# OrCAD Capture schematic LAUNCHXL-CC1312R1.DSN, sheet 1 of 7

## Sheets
1 6_EnergyTrace Power: size A3; title: LAUNCHXL-CC1312R1; rev: B; company: Texas Instruments
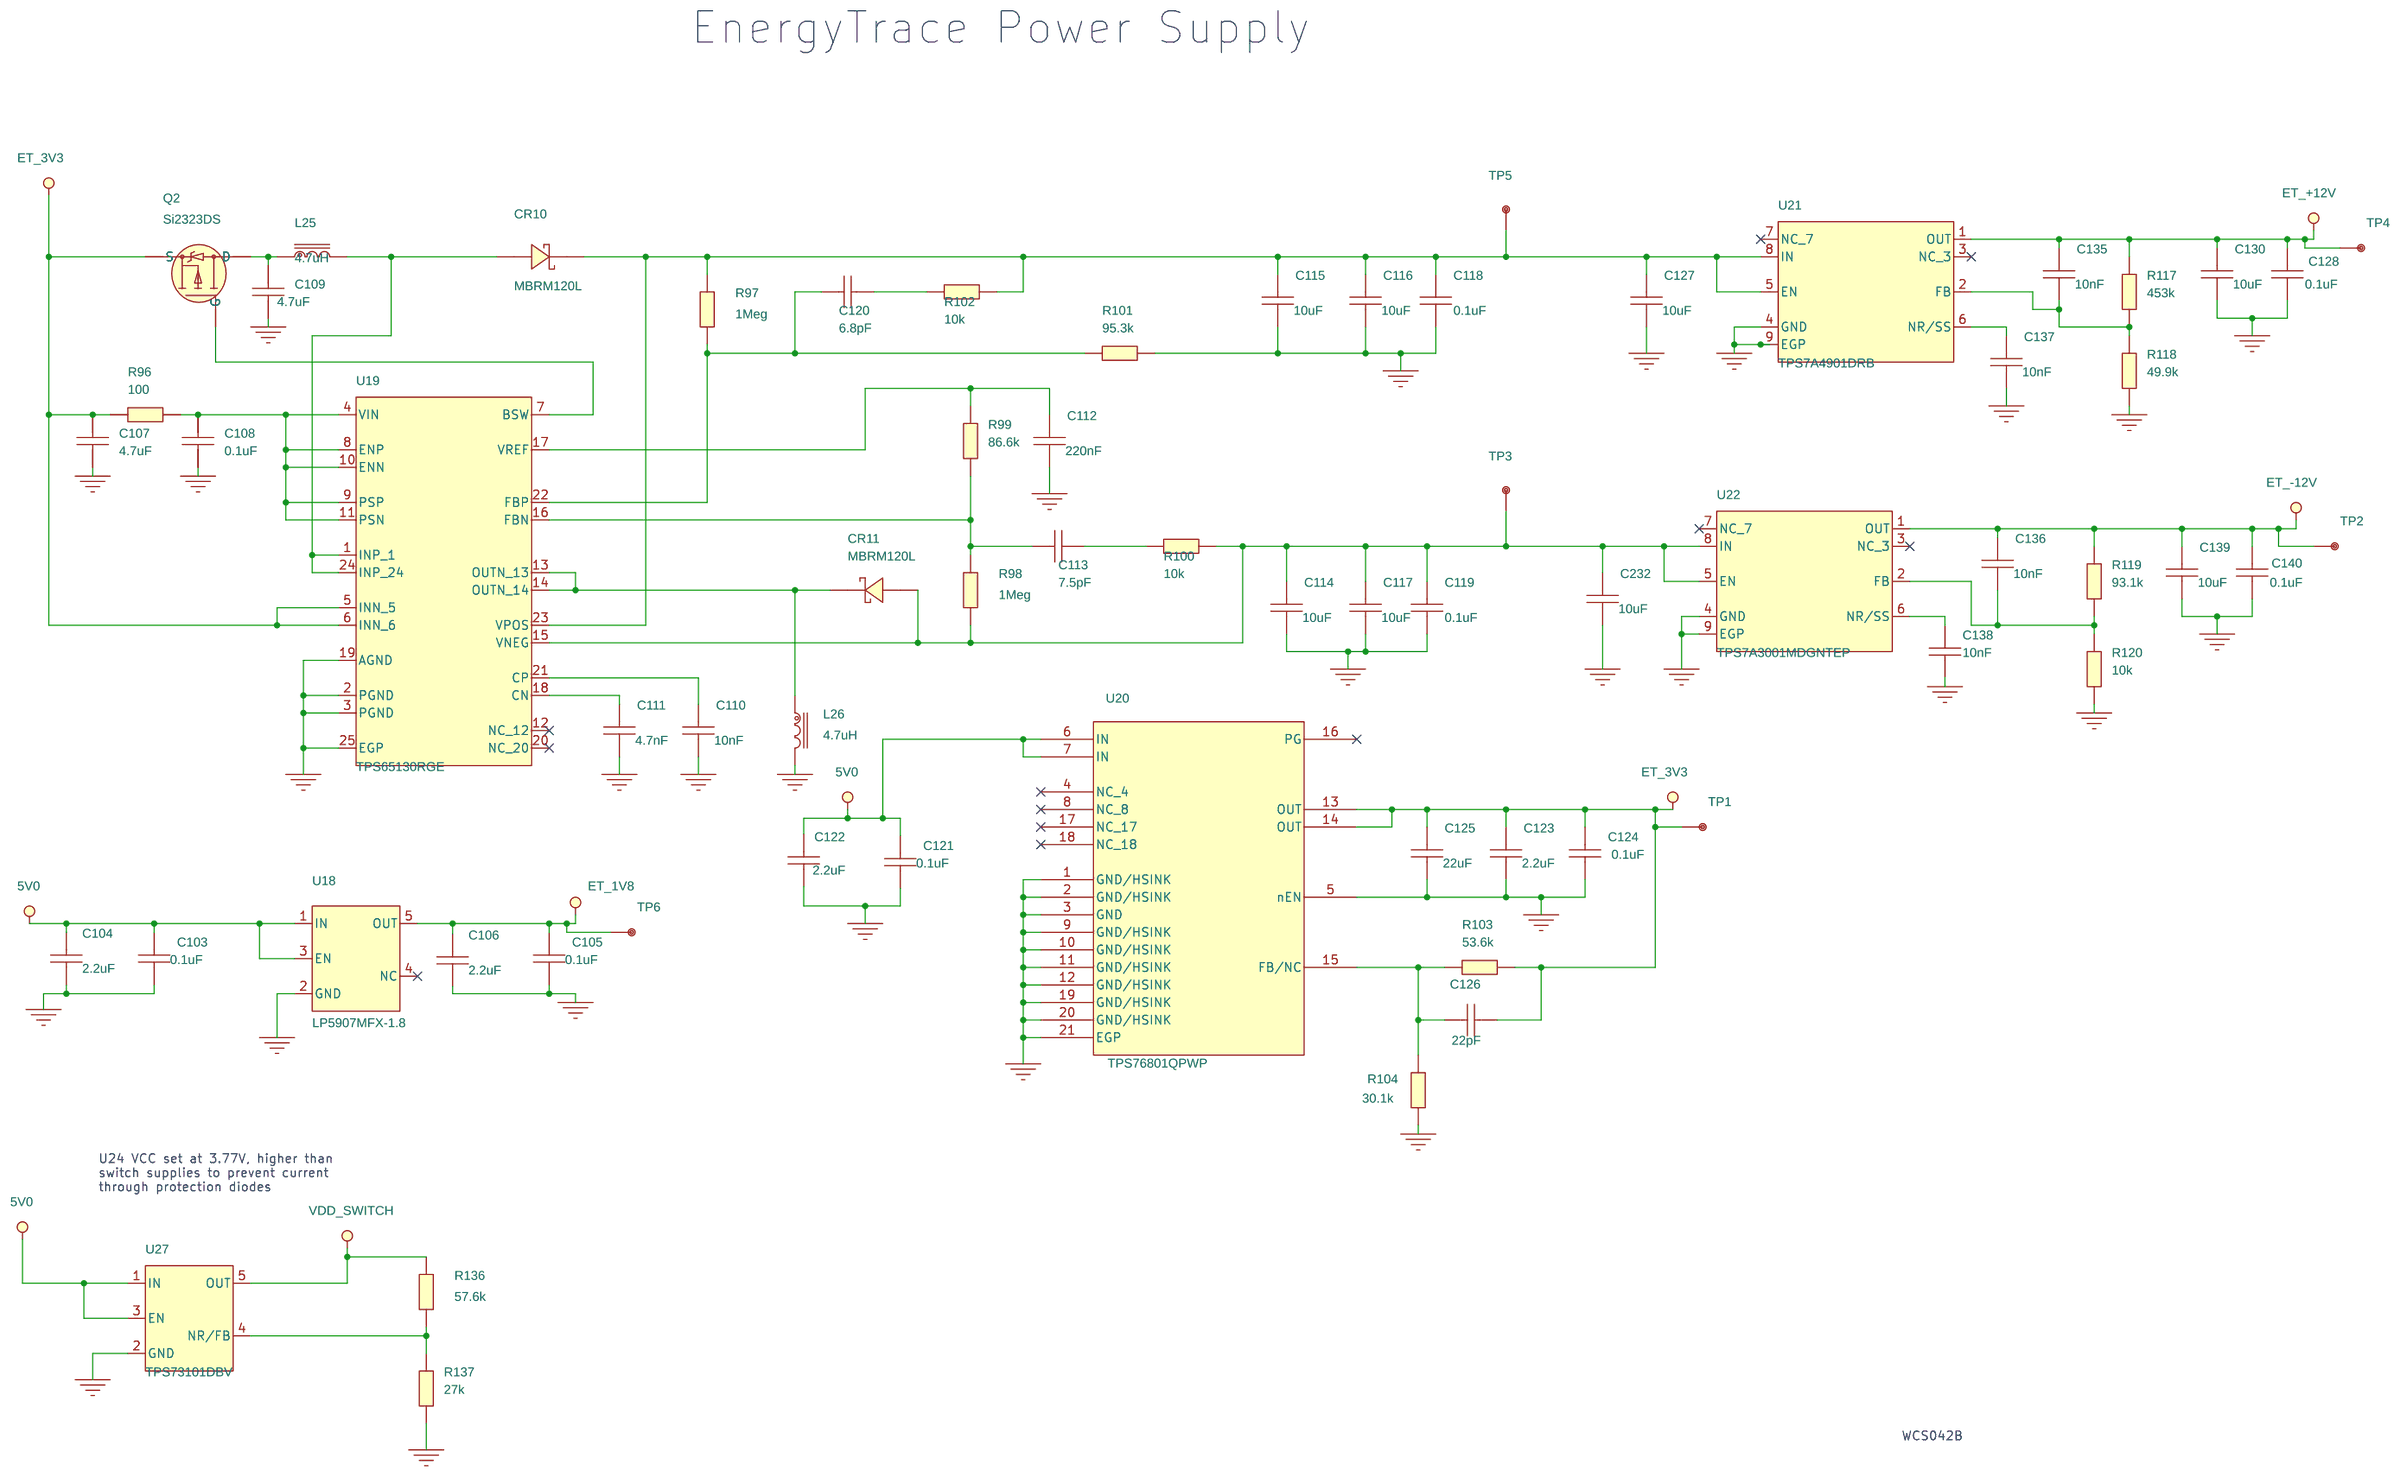
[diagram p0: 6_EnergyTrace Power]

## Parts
C103  0.1uF  [CAPC1005X60B2N]
C104  2.2uF  [CAPC1005X60B2N]
C105  0.1uF  [CAPC1005X60B2N]
C106  2.2uF  [CAPC1005X60B2N]
C107  4.7uF  [CAPC1005X60B2N]
C108  0.1uF  [CAPC1005X60B2N]
C109  4.7uF  [CAPC2012X150A2N]
C110  10nF  [CAPC1005X60B2N]
C111  4.7nF  [CAPC1005X60N]
C112  220nF  [CAPC1005X60A2N]
C113  7.5pF  [CAPC1005X60B2N]
C114  10uF  [CAPC2012X150A2N]
C115  10uF  [CAPC2012X150A2N]
C116  10uF  [CAPC2012X150A2N]
C117  10uF  [CAPC2012X150A2N]
C118  0.1uF  [CAPC1005X60B2N]
C119  0.1uF  [CAPC1005X60B2N]
C120  6.8pF  [CAPC1005X60B2N]
C121  0.1uF  [CAPC1005X60B2N]
C122  2.2uF  [CAPC1005X60B2N]
C123  2.2uF  [CAPC1005X60B2N]
C124  0.1uF  [CAPC1005X60B2N]
C125  22uF  [CAPC1608X100A2N]
C126  22pF  [CAPC1005X60B2N]
C127  10uF  [CAPC2012X150A2N]
C128  0.1uF  [CAPC1005X60B2N]
C130  10uF  [CAPC2012X150A2N]
C135  10nF  [CAPC1005X60B2N]
C136  10nF  [CAPC1005X60B2N]
C137  10nF  [CAPC1005X60B2N]
C138  10nF  [CAPC1005X60B2N]
C139  10uF  [CAPC2012X150A2N]
C140  0.1uF  [CAPC1005X60B2N]
C232  10uF  [CAPC2012X150A2N]
CR10  MBRM120L  [DIO_MBRM120_A2N]
CR11  MBRM120L  [DIO_MBRM120_A2N]
L25  4.7uH  [IND_7447789004N]
L26  4.7uH  [IND_7447789004N]
Q2  Si2323DS  [SOT95P237X130-3N]
R96  100  [RESC1005X40B2N]
R97  1Meg  [RESC1005X40B2N]
R98  1Meg  [RESC1005X40B2N]
R99  86.6k  [RESC1005X40N]
R100  10k  [RESC1005X40B2N]
R101  95.3k  [RESC1005X40N]
R102  10k  [RESC1005X40B2N]
R103  53.6k  [RESC1005X40N]
R104  30.1k  [RESC1005X40N]
R117  453k  [RESC1005X40N]
R118  49.9k  [RESC1005X40N]
R119  93.1k  [RESC1005X40N]
R120  10k  [RESC1005X40A2N]
R136  57.6k  [RESC1005X40A2N]
R137  27k  [RESC1005X40A2N]
TP1  HOLE_0.6mm_PTH  [MTG60_120]
TP2  HOLE_0.6mm_PTH  [MTG60_120]
TP3  HOLE_0.6mm_PTH  [MTG60_120]
TP4  HOLE_0.6mm_PTH  [MTG60_120]
TP5  HOLE_0.6mm_PTH  [MTG60_120]
TP6  HOLE_0.6mm_PTH  [MTG60_120]
U18  LP5907MFX-1.8  [SOT95P280X145-5A2N]
U19  TPS65130RGE  [QFNFC50P400X400X100-25D2N]
U20  TPS76801QPWP  [TSSOP65P640X120-21N]
U21  TPS7A4901DRB  [SON65P300X300X100-9A2N]
U22  TPS7A3001MDGNTEP  [SOP65P490X110-9B2N]
U27  TPS73101DBV  [SOT95P280X145-5A2N]

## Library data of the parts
C103 C105 C108 C118 C119 C121 C124 C128 C140 = CAPACITOR: CAPACITOR, CERAMIC X7R, 0.1uF, 25V, -10%/+10%, -55DEGC/+125DEGC, 0402, SMD; AutoDoc File: https://notefied-dynamic-precision.com/DB/Apps/Desktop/Item/Object.aspx?id=115293; BU Name: TEXAS INSTRUMENTS NORWAY; Client Status: UNDER_REVIEW; Datasheet URL 1: http://psearch.en.murata.com/capacitor/product/GRM155R71E104KE14%23.pdf; Datasheet URL 2: http://search.murata.co.jp/Ceramy/image/img/w_hinm/L0005E.pdf; Dielectric Type: X7R; Last Time Buy: N/A; LifeCycle Status: ACTIVE; MPN: GRM155R70J104KA01D; MPN Status: ACTIVE; Manufacturer: MURATA; Max Oper Temp: +125DEGC; Max Tol: +10%; Min Oper Temp: -55DEGC; Min Tol: -10%; Mounting Type: SMD; NOTE Status: PREFERRED; Old Footprint: CAPC1005X60N,0402; PCB Package: 0402; Packing Size: 10000; Packing Type: TAPE_&_REEL; Part Number: 02-07861; Part Type: CAPACITOR\CERAMIC\0402\STANDARD; REACH/SVHC_COMPLIANCE: COMPLIANT; REACH/SVHC_DETAILS: SVHC LIST VERSION Jun 20, 2016; REACH/SVHC_SOURCE: REACH DECLARATION; REACH/SVHC_STATUS: UNAFFECTED; Revision: R002; RoHS Status: ROHS_COMPLIANT; Rtd Voltage: 25V; Vendor: MURATA; Vendor Part Number: GRM155R71E104KE14D; Vendor Part Status: ACTIVE; WEIGHT: 0.0016g
C104 C106 C122 C123 = CAPACITOR: CAPACITOR, CERAMIC X5R, 2.2uF, 6.3V, -10%/+10%, -55DEGC/+85DEGC, 0402, SMD; AutoDoc File: https://notefied-dynamic-precision.com/DB/Apps/Desktop/Item/Object.aspx?id=113352; BU Name: TEXAS INSTRUMENTS NORWAY; Budget Currency: USD; Budget Price: 0.0126; Country of Origin: PHILIPPINES; Datasheet URL 1: http://psearch.murata.com/capacitor/product/GRM155R60J225KE95%23.pdf; Datasheet URL 2: http://psearch.en.murata.com/capacitor/product/GRM155R60J225KE95%23.html; Dielectric Type: X5R; Last Time Buy: N/A; Lead Time: N/A; Max Oper Temp: +85DEGC; Max Tol: +10%; Min Oper Temp: -55DEGC; Min Tol: -10%; Mounting Type: SMD; PCB Package: 0402; Packing Size: 10000; Packing Type: TAPE_&_REEL; Part Number: 02-07624; Part Type: CAPACITOR\CERAMIC\0402\STANDARD; Revision: R000; RoHS Status: ROHS_COMPLIANT; Rtd Voltage: 6.3V; Vendor: MURATA; Vendor Part Number: GRM155R60J225KE95D; Vendor Part Status: NRND; Weight: 0.0016g
C107 = CAPACITOR: CAPACITOR, CERAMIC X5R, 4.7uF, 6.3V, -20%/+20%, -55DEGC/+85DEGC, 0402, SMD; AutoDoc File: https://notefied-dynamic-precision.com/DB/Apps/Desktop/Item/Object.aspx?id=113357; BU Name: TEXAS INSTRUMENTS NORWAY; Budget Currency: USD; Budget Price: 0.03; Country of Origin: PHILIPPINES; Datasheet URL 1: http://psearch.murata.com/capacitor/product/GRM155R60J475ME87%23.pdf; Datasheet URL 2: http://search.murata.co.jp/Ceramy/image/img/w_hinm/L0005E.pdf; Dielectric Type: X5R; Last Time Buy: N/A; Lead Time: 14; Max Oper Temp: +85DEGC; Max Tol: +20%; Min Oper Temp: -55DEGC; Min Tol: -20%; Mounting Type: SMD; PCB Package: 0402; Packing Size: 10000; Packing Type: TAPE_&_REEL; Part Number: 02-07629; Part Type: CAPACITOR\CERAMIC\0402\STANDARD; REACH/SVHC_COMPLIANCE: COMPLIANT; REACH/SVHC_DETAILS: SVHC LIST VERSION Dec 17, 2015; REACH/SVHC_SOURCE: REACH DECLARATION; REACH/SVHC_STATUS: UNAFFECTED; Revision: R000; RoHS Status: ROHS_COMPLIANT; Rtd Voltage: 6.3V; Vendor: MURATA; Vendor Part Number: GRM155R60J475ME87D; Vendor Part Status: NRND; Weight: 0.0025g
C109 = CAPACITOR: CAPACITOR, CERAMIC X7R, 4.7uF, 25V, -10%/+10%, -55DEGC/+125DEGC, 0805, SMD; ALT_SYMBOLS: CAPC2012X150A2L,CAPC2012X150A2M; AutoDoc File: https://notefied-dynamic-precision.com/DB/Apps/Desktop/Item/Object.aspx?id=100426; BU Name: DYNAMIC PRECISION GDANSK; Budget Currency: EUR; Budget Price: 0.165; Client Status: UNDER_REVIEW; Country of Origin: JAPAN,CHINA; Datasheet URL 1: http://product.tdk.com/info/en/documents/chara_sheet/C2012X7R1E475K125AB.pdf; Datasheet URL 2: http://product.tdk.com/info/en/catalog/datasheets/mlcc_commercial_general_en.pdf; Dielectric Type: X7R; Last Time Buy: N/A; Lead Time: 14; Max Oper Temp: +125DEGC; Max Tol: +10%; Min Oper Temp: -55DEGC; Min Tol: -10%; Mounting Type: SMD; PCB Package: 0805; Packing Size: 2000; Packing Type: TAPE_&_REEL; Part Number: 02-06852; Part Type: CAPACITOR\CERAMIC\0805\STANDARD; Revision: R001; RoHS Status: ROHS_COMPLIANT; Rtd Voltage: 25V; Vendor: TDK; Vendor Part Number: C2012X7R1E475K125AB; Vendor Part Status: ACTIVE; Weight: 0.01563g
C110 C135-C138 = CAPACITOR: CAPACITOR, CERAMIC X7R, 10nF, 25V, -10%/+10%, -55DEGC/+125DEGC, 0402, SMD; AutoDoc File: https://notefied-dynamic-precision.com/DB/Apps/Desktop/Item/Object.aspx?id=114570; BU Name: TEXAS INSTRUMENTS NORWAY; Budget Currency: EUR; Budget Price: 0.003; Client Status: UNDER_REVIEW; Country of Origin: JAPAN,CHINA; Datasheet URL 1: http://psearch.murata.com/capacitor/product/GRM155R71E103KA01%23.pdf; Datasheet URL 2: http://search.murata.co.jp/Ceramy/image/img/w_hinm/L0005E.pdf; Definied Quality: INDUSTRIAL; Dielectric Type: X7R; Esd Level: N/A; Last Time Buy: N/A; Lead Time: 18; LifeCycle Status: ACTIVE; MPN: CAPACITOR_0402_10nF_X7R_M_+/-10%_25V; MPN Status: ACTIVE; MSL: N/A; MTBF: N/A; MTBF Standard: N/A; Manufacturer: MANUFACTURER SELECTION; Max Oper Temp: +125DEGC; Max Tol: +10%; Min Oper Temp: -55DEGC; Min Tol: -10%; Mounting Type: SMD; NOTE Status: PREFERRED; Old Footprint: CAPC1005X60N; PCB Package: 0402; Packing Size: 10000; Packing Type: TAPE_&_REEL; Part Number: 02-07775; Part Type: CAPACITOR\CERAMIC\0402\STANDARD; REACH/SVHC_COMPLIANCE: COMPLIANT; REACH/SVHC_DETAILS: SVHC LIST VERSION Dec 17, 2015; REACH/SVHC_SOURCE: MATERIAL DECLARATION; REACH/SVHC_STATUS: UNAFFECTED; Revision: R000; RoHS Status: ROHS_COMPLIANT; Rtd Voltage: 25V; Vendor: MURATA; Vendor Part Number: GRM155R71E103KA01D; Vendor Part Status: ACTIVE; WEIGHT: 0.0016g
C111 = CAPACITOR: CAPACITOR, CERAMIC X7R, 4.7nF, 25V, -10%/+10%, -55DEGC/+125DEGC, 0402, SMD; ALT_SYMBOLS: CAPC1005X60L,CAPC1005X60M; AutoDoc File: https://notefied-dynamic-precision.com/DB/Apps/Desktop/Item/Object.aspx?id=72152; BU Name: DYNAMIC PRECISION GDANSK; Budget Currency: EUR; Budget Price: 0.006; Client Status: UNDER_REVIEW; Country of Origin: PHILIPPINES,CHINA; Datasheet URL 1: http://psearch.murata.com/capacitor/product/GRM155R71E472KA01%23.pdf; Datasheet URL 2: http://search.murata.co.jp/Ceramy/image/img/w_hinm/L0005E.pdf; Dielectric Type: X7R; Last Time Buy: N/A; Lead Time: 18; Max Oper Temp: +125DEGC; Max Tol: +10%; Min Oper Temp: -55DEGC; Min Tol: -10%; Mounting Type: SMD; PCB Package: 0402; Packing Size: 10000; Packing Type: TAPE_&_REEL; Part Number: 02-02074; Part Type: CAPACITOR\CERAMIC\0402\STANDARD; Revision: R002; RoHS Status: ROHS_COMPLIANT; Rtd Voltage: 25V; Vendor: MURATA; Vendor Part Number: GRM155R71E472KA01D; Vendor Part Status: NRND; Weight: 0.0016g
C112 = CAPACITOR: CAPACITOR, CERAMIC X7R, 220nF, 16V, -10%/+10%, -55DEGC/+125DEGC, 0402, SMD; ALT_SYMBOLS: CAPC1005X60A2L,CAPC1005X60A2M; AutoDoc File: https://notefied-dynamic-precision.com/DB/Apps/Desktop/Item/Object.aspx?id=84559; BU Name: DYNAMIC PRECISION GDANSK; Budget Currency: EUR; Budget Price: 0.019; Client Status: UNDER_REVIEW; Country of Origin: CHINA; Datasheet URL 1: http://psearch.murata.com/capacitor/product/GRM155R71C224KA12%23.pdf; Datasheet URL 2: http://search.murata.co.jp/Ceramy/image/img/w_hinm/L0005E.pdf; Dielectric Type: X7R; Last Time Buy: N/A; Lead Time: 16; Max Oper Temp: +125DEGC; Max Tol: +10%; Min Oper Temp: -55DEGC; Min Tol: -10%; Mounting Type: SMD; PCB Package: 0402; Packing Size: 10000; Packing Type: TAPE_&_REEL; Part Number: 02-04132; Part Type: CAPACITOR\CERAMIC\0402\STANDARD; Revision: R003; RoHS Status: ROHS_COMPLIANT; Rtd Voltage: 16V; Vendor: MURATA; Vendor Part Number: GRM155R71C224KA12D; Vendor Part Status: ACTIVE; Weight: 0.0016g
C113 = CAPACITOR: CAPACITOR, CERAMIC C0G/NP0, 7.5pF, 50V, -0.25pF/+0.25pF, -55DEGC/+125DEGC, 0402, SMD; AutoDoc File: https://notefied-dynamic-precision.com/DB/Apps/Desktop/Item/Object.aspx?id=90841; BU Name: TEXAS INSTRUMENTS NORWAY; Budget Currency: EUR; Budget Price: 0.006; Client Status: UNDER_REVIEW; Country of Origin: PHILIPPINES; Datasheet URL 1: http://psearch.murata.com/capacitor/product/GRM1555C1H7R5CA01%23.pdf; Datasheet URL 2: http://search.murata.co.jp/Ceramy/image/img/w_hinm/L0005E.pdf; Dielectric Type: C0G/NP0; Last Time Buy: N/A; Lead Time: 14; Max Oper Temp: +125DEGC; Max Tol: +0.25pF; Min Oper Temp: -55DEGC; Min Tol: -0.25pF; Mounting Type: SMD; PCB Package: 0402; Packing Size: 10000; Packing Type: TAPE_&_REEL; Part Number: 02-05033; Part Type: CAPACITOR\CERAMIC\0402\STANDARD; REACH/SVHC_COMPLIANCE: COMPLIANT; REACH/SVHC_DETAILS: SVHC LIST VERSION Dec 17, 2015; REACH/SVHC_SOURCE: REACH DECLARATION; REACH/SVHC_STATUS: UNAFFECTED; Revision: R002; RoHS Status: ROHS_COMPLIANT; Rtd Voltage: 50V; Vendor: MURATA; Vendor Part Number: GRM1555C1H7R5CA01D; Vendor Part Status: ACTIVE; Weight: 0.0016g
C114-C117 C127 C130 C139 C232 = CAPACITOR: CAPACITOR, CERAMIC X5R, 10uF, 35V, -10%/+10%, -55DEGC/+85DEGC, 0805, SMD; ALT_SYMBOLS: CAPC2012X150A2L,CAPC2012X150A2M; AutoDoc File: https://notefied-dynamic-precision.com/DB/Apps/Desktop/Item/Object.aspx?id=88855; BU Name: DYNAMIC PRECISION GDANSK; Budget Currency: EUR; Budget Price: 0.206; Client Status: UNDER_REVIEW; Country of Origin: CHINA,JAPAN; Datasheet URL 1: http://product.tdk.com/capacitor/mlcc/class/print_detail_pdf.php?lang=en&part_no=C2012X5R1V106K085AC; Datasheet URL 2: http://product.tdk.com/info/en/catalog/datasheets/mlcc_commercial_general_en.pdf; Dielectric Type: X5R; Last Time Buy: N/A; Lead Time: 16; Max Oper Temp: +85DEGC; Max Tol: +10%; Min Oper Temp: -55DEGC; Min Tol: -10%; Mounting Type: SMD; PCB Package: 0805; Packing Size: 4000; Packing Type: TAPE_&_REEL; Part Number: 02-04831; Part Type: CAPACITOR\CERAMIC\0805\STANDARD; Revision: R002; RoHS Status: ROHS_COMPLIANT; Rtd Voltage: 35V; Vendor: TDK; Vendor Part Number: C2012X5R1V106K085AC; Vendor Part Status: ACTIVE; Weight: 0.01563g
C120 = CAPACITOR: CAPACITOR, CERAMIC C0G/NP0, 6.8pF, 50V, -0.25pF/+0.25pF, -55DEGC/+125DEGC, 0402, SMD; AutoDoc File: https://notefied-dynamic-precision.com/DB/Apps/Desktop/Item/Object.aspx?id=113346; BU Name: TEXAS INSTRUMENTS NORWAY; Budget Currency: EUR; Budget Price: 0.007; Country of Origin: PHILIPPINES; Datasheet URL 1: http://psearch.murata.com/capacitor/product/GRM1555C1H6R8CA01%23.pdf; Datasheet URL 2: http://search.murata.co.jp/Ceramy/image/img/w_hinm/L0005E.pdf; Dielectric Type: C0G/NP0; Last Time Buy: N/A; Lead Time: 16; Max Oper Temp: +125DEGC; Max Tol: +0.25pF; Min Oper Temp: -55DEGC; Min Tol: -0.25pF; Mounting Type: SMD; PCB Package: 0402; Packing Size: 10000; Packing Type: TAPE_&_REEL; Part Number: 02-07618; Part Type: CAPACITOR\CERAMIC\0402\STANDARD; REACH/SVHC_COMPLIANCE: COMPLIANT; REACH/SVHC_DETAILS: SVHC LIST VERSION Dec 17, 2015; REACH/SVHC_SOURCE: REACH DECLARATION; REACH/SVHC_STATUS: UNAFFECTED; Revision: R000; RoHS Status: ROHS_COMPLIANT; Rtd Voltage: 50V; Vendor: MURATA; Vendor Part Number: GRM1555C1H6R8CA01D; Vendor Part Status: ACTIVE; Weight: 0.0016g
C125 = CAPACITOR: CAPACITOR, CERAMIC, X5R, 22uF, 6.3V, -20%/+20%, -55DEGC/+85DEGC, 0603, SMD; ALT_SYMBOLS: CAPC1608X100A2L,CAPC1608X100A2M; AutoDoc File: https://notefied-dynamic-precision.com/DB/Apps/Desktop/Item/Object.aspx?id=104385; BU Name: DYNAMIC PRECISION GDANSK; Budget Currency: EUR; Budget Price: 0.062; Client Status: UNDER_REVIEW; Country of Origin: JAPAN; Datasheet URL 1: http://psearch.murata.com/capacitor/product/GRM188R60J226MEA0%23.pdf; Datasheet URL 2: http://search.murata.co.jp/Ceramy/image/img/w_hinm/L0005E.pdf; Dielectric Type: X5R; Last Time Buy: N/A; Lead Time: 26; Max Oper Temp: +85DEGC; Max Tol: +20%; Min Oper Temp: -55DEGC; Min Tol: -20%; Mounting Type: SMD; PCB Package: 0603; Packing Size: 4000; Packing Type: TAPE_&_REEL; Part Number: 02-07053; Part Type: CAPACITOR\CERAMIC\0603\STANDARD; REACH/SVHC_COMPLIANCE: COMPLIANT; REACH/SVHC_DETAILS: SVHC LIST VERSION Dec 17, 2015; REACH/SVHC_SOURCE: REACH DECLARATION; REACH/SVHC_STATUS: UNAFFECTED; Revision: R001; RoHS Status: ROHS_COMPLIANT; Rtd Voltage: 6.3V; Vendor: MURATA; Vendor Part Number: GRM188R60J226MEA0D; Vendor Part Status: ACTIVE; Weight: 0.0091g
C126 = CAPACITOR: CAPACITOR, CERAMIC C0G/NP0, 22pF, 25V, -5%/+5%, -55DEGC/+125DEGC, 0402, SMD; AutoDoc File: https://notefied-dynamic-precision.com/DB/Apps/Desktop/Item/Object.aspx?id=114988; BU Name: TEXAS INSTRUMENTS NORWAY; Client Status: UNDER_REVIEW; Datasheet URL 1: http://psearch.en.murata.com/capacitor/product/GRT1555C1E220JA02%23.pdf?graph=c7db757067d5d67a2d7f1582efacb8f6; Datasheet URL 2: N/A; Dielectric Type: C0G/NP0; Max Oper Temp: +125DEGC; Max Tol: +5%; Min Oper Temp: -55DEGC; Min Tol: -5%; Mounting Type: SMD; PCB Package: 0402; Packing Size: 10000; Packing Type: TAPE_&_REEL; Part Number: 02-07830; Part Type: CAPACITOR\CERAMIC\0402\STANDARD; Revision: R001; RoHS Status: ROHS_COMPLIANT; Rtd Voltage: 25V; Vendor: MURATA; Vendor Part Number: GRT1555C1E220JA02D; Vendor Part Status: ACTIVE; Weight: 0.0016g
CR10 CR11 = DIODE_SCH_0: DIODE, SCHOTTKY POWER RECTIFIER, 20V, 1A, -55DEGC/+125DEGC, SMD; ALT_SYMBOLS: DIO_MBRM120_A2L,DIO_MBRM120_A2M; AutoDoc File: https://notefied-dynamic-precision.com/DB/Apps/Desktop/Item/Object.aspx?id=54665; BU Name: DYNAMIC PRECISION GDANSK; Budget Currency: USD; Budget Price: 0.12; Client Status: UNDER_REVIEW; Country of Origin: UNITED STATES; Datasheet URL 1: http://www.onsemi.com/pub/Collateral/MBRM120L-D.PDF; Datasheet URL 2: http://www.onsemi.com/pub/Collateral/457-04.PDF; Last Time Buy: N/A; Lead Time: 5; Max Oper Temp: +125DEGC; Min Oper Temp: -55DEGC; Mounting Type: SMD; Packing Size: 12000; Packing Type: TAPE_&_REEL; Part Number: 14-03151; Part Type: DIODE\SCHOTTKY; Revision: R002; RoHS Status: ROHS_COMPLIANT; Rtd Current: 1A; Rtd Voltage: 20V; Vendor: ON SEMICONDUCTOR; Vendor Part Number: MBRM120LT3G; Vendor Part Status: ACTIVE; Weight: 0.0163g
L25 L26 = IND_HOR_0: INDUCTOR, POWER, FERRITE CORE, SHIELDED, 4.7uH, -20%/+20%, 3.9A, -40DEGC/+125DEGC, SMD; ALT_SYMBOLS: IND_7447789004L,IND_7447789004M; AutoDoc File: https://notefied-dynamic-precision.com/DB/Apps/Desktop/Item/Object.aspx?id=96788; BU Name: DYNAMIC PRECISION GDANSK; Budget Currency: EUR; Budget Price: 2.00; Client Status: UNDER_REVIEW; Core Material: FERRITE; Country of Origin: CHINA; Datasheet URL 1: http://katalog.we-online.de/pbs/datasheet/7447789004.pdf; Datasheet URL 2: N/A; Frequency: 30MHz; Last Time Buy: N/A; Lead Time: 3; Max Oper Temp: +125DEGC; Max Tol: +20%; Min Oper Temp: -40DEGC; Min Tol: -20%; Mounting Type: SMD; Packing Size: 1000; Packing Type: TAPE_&_REEL; Part Number: 03-06905; Part Type: INDUCTOR\POWER\OTHER_SMD; Resistance: 0.033; Revision: R001; RoHS Status: ROHS_COMPLIANT; Rtd Current: 3.9A; Vendor: WURTH; Vendor Part Number: 7447789004; Vendor Part Status: ACTIVE; Weight: 1g
Q2 = MOSFET_P_SI2323DS_SOT23-3: TRANSISTOR, MOSFET, P-CHANNEL, -20V, -3.7A, 0.75W, SOT23-3, SMD; ALT_SYMBOLS: SOT95P237X130-3L,SOT95P237X130-3M; AutoDoc File: https://notefied-dynamic-precision.com/DB/Apps/Desktop/Item/Object.aspx?id=17405; BU Name: DYNAMIC PRECISION GDANSK; Budget Currency: EUR; Budget Price: 0.20; Client Status: UNDER_REVIEW; Country of Origin: CHINA; Datasheet URL 1: http://www.vishay.com/docs/72024/72024.pdf; Datasheet URL 2: N/A; Last Time Buy: N/A; Lead Time: 24; Max Oper Temp: +150DEGC; Min Oper Temp: -55DEGC; Mounting Type: SMD; PCB Package: SOT23-3; Packing Size: 3000; Packing Type: TAPE_&_REEL; Part Number: 16-02946; Part Type: TRANSISTOR\UNIPOLAR\FET\MOSFET\P-CHANNEL; Revision: R003; RoHS Status: ROHS_COMPLIANT; Rtd Current: -3.7A; Rtd Power: 0.75W; Rtd Voltage: -20V; Vendor: VISHAY; Vendor Part Number: SI2323DS-T1-E3; Vendor Part Status: NRND; Weight: N/A
R96 = RESISTOR: RESISTOR, THICK FILM, 100, -5%/+5%, 0.063W, 50V, -55DEGC/+155DEGC, 0402, SMD; AutoDoc File: https://notefied-dynamic-precision.com/DB/Apps/Desktop/Item/Object.aspx?id=114555; BU Name: TEXAS INSTRUMENTS NORWAY; Budget Currency: USD; Budget Price: 0.0014; Client Status: UNDER_REVIEW; Country of Origin: UNITED STATES; Datasheet URL 1: http://www.vishay.com/docs/20035/dcrcwe3.pdf; Datasheet URL 2: N/A; Definied Quality: INDUSTRIAL; Esd Level: N/A; Last Time Buy: N/A; Lead Time: 16; LifeCycle Status: ACTIVE; MPN: RESISTOR_0402_100_+/-5%_50V_0.063W_M_+/-200ppm; MPN Status: ACTIVE; MSL: N/A; MTBF: N/A; MTBF Standard: N/A; Manufacturer: MANUFACTURER SELECTION; Max Oper Temp: +155DEGC; Max TC: +200PPM/DEGC; Max Tol: +5%; Min Oper Temp: -55DEGC; Min TC: -200PPM/DEGC; Min Tol: -5%; Mounting Type: SMD; NOTE Status: PREFERRED; Old Footprint: RESC1005X40N; PCB Package: 0402; Packing Size: 10000; Packing Type: TAPE_&_REEL; Part Number: 01-22482; Part Type: RESISTOR\0402\STANDARD; REACH/SVHC_COMPLIANCE: COMPLIANT; REACH/SVHC_DETAILS: SVHC LIST VERSION Jun 20, 2016; REACH/SVHC_SOURCE: MATERIAL DECLARATION; REACH/SVHC_STATUS: UNAFFECTED; Resistor Type: THICK FILM; Revision: R000; RoHS Status: ROHS_COMPLIANT; Rtd Current: N/A; Rtd Power: 0.063W; Rtd Voltage: 50V; Vendor: VISHAY; Vendor Part Number: CRCW0402100RJNED; Vendor Part Status: ACTIVE; WEIGHT: 0.00065g
R97 R98 = RESISTOR: RESISTOR, THICK FILM, 1M, -1%/+1%, 0.063W, 50V, -55DEGC/+155DEGC, 0402, SMD; AutoDoc File: https://notefied-dynamic-precision.com/DB/Apps/Desktop/Item/Object.aspx?id=114549; BU Name: TEXAS INSTRUMENTS NORWAY; Budget Currency: EUR; Budget Price: 0.012; Client Status: UNDER_REVIEW; Country of Origin: ISRAEL; Datasheet URL 1: http://www.vishay.com/docs/20035/dcrcwe3.pdf; Datasheet URL 2: N/A; Last Time Buy: N/A; Lead Time: 14; Max Oper Temp: +155DEGC; Max TC: +100PPM/DEGC; Max Tol: +1%; Min Oper Temp: -55DEGC; Min TC: -100PPM/DEGC; Min Tol: -1%; Mounting Type: SMD; PCB Package: 0402; Packing Size: 10000; Packing Type: TAPE_&_REEL; Part Number: 01-22476; Part Type: RESISTOR\0402\PRECISION; Resistance: 1M; Resistor Type: THICK FILM; Revision: R000; RoHS Status: ROHS_COMPLIANT_WITH_EXEMPTION; Rtd Current: N/A; Rtd Power: 0.063W; Rtd Voltage: 50V; Vendor: VISHAY; Vendor Part Number: CRCW04021M00FKED; Vendor Part Status: ACTIVE; Weight: 0.00060916g
R99 = RESISTOR: RESISTOR, THICK FILM, 86.6k, -1%/+1%, 0.063W, 50V, -55DEGC/+155DEGC, 0402, SMD; ALT_SYMBOLS: RESC1005X40L,RESC1005X40M; AutoDoc File: https://notefied-dynamic-precision.com/DB/Apps/Desktop/Item/Object.aspx?id=59478; BU Name: DYNAMIC PRECISION GDANSK; Budget Currency: EUR; Budget Price: 0.012; Client Status: UNDER_REVIEW; Country of Origin: ISRAEL; Datasheet URL 1: http://www.vishay.com/docs/20035/dcrcwe3.pdf; Datasheet URL 2: N/A; Last Time Buy: N/A; Lead Time: 14; Max Oper Temp: +155DEGC; Max TC: +100PPM/DEGC; Max Tol: +1%; Min Oper Temp: -55DEGC; Min TC: -100PPM/DEGC; Min Tol: -1%; Mounting Type: SMD; PCB Package: 0402; Packing Size: 10000; Packing Type: TAPE_&_REEL; Part Number: 01-04671; Part Type: RESISTOR\0402\PRECISION; Resistor Type: THICK FILM; Revision: R002; RoHS Status: ROHS_COMPLIANT_WITH_EXEMPTION; Rtd Current: N/A; Rtd Power: 0.063W; Rtd Voltage: 50V; Vendor: VISHAY; Vendor Part Number: CRCW040286K6FKED; Vendor Part Status: ACTIVE; Weight: 0.00065g
R100 R102 = RESISTOR: RESISTOR, THICK FILM, 10k, -5%/+5%, 0.063W, 50V, -55DEGC/+155DEGC, 0402, SMD; AutoDoc File: https://notefied-dynamic-precision.com/DB/Apps/Desktop/Item/Object.aspx?id=113326; BU Name: TEXAS INSTRUMENTS NORWAY; Budget Currency: EUR; Budget Price: 0.014; Client Status: UNDER_REVIEW; Country of Origin: ISRAEL; Datasheet URL 1: http://www.vishay.com/docs/20035/dcrcwe3.pdf; Datasheet URL 2: N/A; Definied Quality: INDUSTRIAL; Esd Level: N/A; Last Time Buy: N/A; Lead Time: 18; LifeCycle Status: ACTIVE; MPN: RESISTOR_0402_10k_+/-5%_50V_0.063W_M_+/-200ppm; MPN Status: ACTIVE; MSL: N/A; MTBF: N/A; MTBF Standard: N/A; Manufacturer: MANUFACTURER SELECTION; Max Oper Temp: +155DEGC; Max TC: +200PPM/DEGC; Max Tol: +5%; Min Oper Temp: -55DEGC; Min TC: -200PPM/DEGC; Min Tol: -5%; Mounting Type: SMD; NOTE Status: PREFERRED; Old Footprint: RESC1005X40N; PCB Package: 0402; Packing Size: 10000; Packing Type: TAPE_&_REEL; Part Number: 01-22353; Part Type: RESISTOR\0402\STANDARD; REACH/SVHC_COMPLIANCE: COMPLIANT; REACH/SVHC_DETAILS: SVHC LIST VERSION Jun 20, 2016; REACH/SVHC_SOURCE: MATERIAL DECLARATION; REACH/SVHC_STATUS: UNAFFECTED; Resistor Type: THICK FILM; Revision: R001; RoHS Status: ROHS_COMPLIANT_WITH_EXEMPTION; Rtd Current: N/A; Rtd Power: 0.063W; Rtd Voltage: 50V; Vendor: VISHAY; Vendor Part Number: CRCW040210K0JNED; Vendor Part Status: ACTIVE; WEIGHT: 0.00065g
R101 = RESISTOR: RESISTOR, THICK FILM, 95.3k, -1%/+1%, 0.063W, 50V, -55DEGC/+155DEGC, 0402, SMD; ALT_SYMBOLS: RESC1005X40L,RESC1005X40M; AutoDoc File: https://notefied-dynamic-precision.com/DB/Apps/Desktop/Item/Object.aspx?id=59481; BU Name: DYNAMIC PRECISION GDANSK; Budget Currency: USD; Budget Price: 0.0022; Country of Origin: MEXICO; Datasheet URL 1: http://www.vishay.com/docs/20035/dcrcwe3.pdf; Datasheet URL 2: N/A; Last Time Buy: N/A; Lead Time: 16; Max Oper Temp: +155DEGC; Max TC: +100PPM/DEGC; Max Tol: +1%; Min Oper Temp: -55DEGC; Min TC: -100PPM/DEGC; Min Tol: -1%; Mounting Type: SMD; PCB Package: 0402; Packing Size: 10000; Packing Type: TAPE_&_REEL; Part Number: 01-04674; Part Type: RESISTOR\0402\PRECISION; Resistor Type: THICK FILM; Revision: R001; RoHS Status: ROHS_COMPLIANT; Rtd Current: N/A; Rtd Power: 0.063W; Rtd Voltage: 50V; Vendor: VISHAY; Vendor Part Number: CRCW040295K3FKED; Vendor Part Status: ACTIVE; Weight: 0.00065g
R103 = RESISTOR: RESISTOR, THICK FILM, 53.6k, -1%/+1%, 0.063W, 50V, -55DEGC/+155DEGC, 0402, SMD; ALT_SYMBOLS: RESC1005X40L,RESC1005X40M; AutoDoc File: https://notefied-dynamic-precision.com/DB/Apps/Desktop/Item/Object.aspx?id=59461; BU Name: DYNAMIC PRECISION GDANSK; Budget Currency: EUR; Budget Price: 0.016; Country of Origin: ISRAEL; Datasheet URL 1: http://www.vishay.com/docs/20035/dcrcwe3.pdf; Datasheet URL 2: N/A; Last Time Buy: N/A; Lead Time: 16; Max Oper Temp: +155DEGC; Max TC: +100PPM/DEGC; Max Tol: +1%; Min Oper Temp: -55DEGC; Min TC: -100PPM/DEGC; Min Tol: -1%; Mounting Type: SMD; PCB Package: 0402; Packing Size: 10000; Packing Type: TAPE_&_REEL; Part Number: 01-04654; Part Type: RESISTOR\0402\PRECISION; Resistor Type: THICK FILM; Revision: R001; RoHS Status: ROHS_COMPLIANT; Rtd Current: N/A; Rtd Power: 0.063W; Rtd Voltage: 50V; Vendor: VISHAY; Vendor Part Number: CRCW040253K6FKED; Vendor Part Status: ACTIVE; Weight: 0.00065g
R104 = RESISTOR: RESISTOR, THICK FILM, 30.1k, -1%/+1%, 0.063W, 50V, -55DEGC/+155DEGC, 0402, SMD; ALT_SYMBOLS: RESC1005X40L,RESC1005X40M; AutoDoc File: https://notefied-dynamic-precision.com/DB/Apps/Desktop/Item/Object.aspx?id=59439; BU Name: DYNAMIC PRECISION GDANSK; Budget Currency: EUR; Budget Price: 0.012; Client Status: UNDER_REVIEW; Country of Origin: ISRAEL; Datasheet URL 1: http://www.vishay.com/docs/20035/dcrcwe3.pdf; Datasheet URL 2: N/A; Last Time Buy: N/A; Lead Time: 14; Max Oper Temp: +155DEGC; Max TC: +100PPM/DEGC; Max Tol: +1%; Min Oper Temp: -55DEGC; Min TC: -100PPM/DEGC; Min Tol: -1%; Mounting Type: SMD; PCB Package: 0402; Packing Size: 10000; Packing Type: TAPE_&_REEL; Part Number: 01-04632; Part Type: RESISTOR\0402\PRECISION; Resistor Type: THICK FILM; Revision: R002; RoHS Status: ROHS_COMPLIANT_WITH_EXEMPTION; Rtd Current: N/A; Rtd Power: 0.063W; Rtd Voltage: 50V; Vendor: VISHAY; Vendor Part Number: CRCW040230K1FKED; Vendor Part Status: ACTIVE; Weight: 0.00060916g
R117 = RESISTOR: RESISTOR, THICK FILM, 453k, -1%/+1%, 0.063W, 50V, -55DEGC/+155DEGC, 0402, SMD; ALT_SYMBOLS: RESC1005X40L,RESC1005X40M; AutoDoc File: https://notefied-dynamic-precision.com/DB/Apps/Desktop/Item/Object.aspx?id=59538; BU Name: DYNAMIC PRECISION GDANSK; Budget Currency: USD; Budget Price: 0.02; Country of Origin: ISRAEL; Datasheet URL 1: http://www.vishay.com/docs/20035/dcrcwe3.pdf; Datasheet URL 2: N/A; Last Time Buy: N/A; Lead Time: 16; Max Oper Temp: +155DEGC; Max TC: +100PPM/DEGC; Max Tol: +1%; Min Oper Temp: -55DEGC; Min TC: -100PPM/DEGC; Min Tol: -1%; Mounting Type: SMD; PCB Package: 0402; Packing Size: 10000; Packing Type: TAPE_&_REEL; Part Number: 01-04731; Part Type: RESISTOR\0402\PRECISION; Resistor Type: THICK FILM; Revision: R001; RoHS Status: ROHS_COMPLIANT; Rtd Current: N/A; Rtd Power: 0.063W; Rtd Voltage: 50V; Vendor: VISHAY; Vendor Part Number: CRCW0402453KFKED; Vendor Part Status: ACTIVE; Weight: 0.00065g
R118 = RESISTOR: RESISTOR, THICK FILM, 49.9k, -1%/+1%, 0.063W, 50V, -55DEGC/+155DEGC, 0402, SMD; ALT_SYMBOLS: RESC1005X40L,RESC1005X40M; AutoDoc File: https://notefied-dynamic-precision.com/DB/Apps/Desktop/Item/Object.aspx?id=59458; BU Name: DYNAMIC PRECISION GDANSK; Budget Currency: EUR; Budget Price: 0.012; Client Status: UNDER_REVIEW; Country of Origin: MEXICO; Datasheet URL 1: http://www.vishay.com/docs/20035/dcrcwe3.pdf; Datasheet URL 2: N/A; Last Time Buy: N/A; Lead Time: 14; Max Oper Temp: +155DEGC; Max TC: +100PPM/DEGC; Max Tol: +1%; Min Oper Temp: -55DEGC; Min TC: -100PPM/DEGC; Min Tol: -1%; Mounting Type: SMD; PCB Package: 0402; Packing Size: 10000; Packing Type: TAPE_&_REEL; Part Number: 01-04651; Part Type: RESISTOR\0402\PRECISION; Resistor Type: THICK FILM; Revision: R001; RoHS Status: ROHS_COMPLIANT_WITH_EXEMPTION; Rtd Current: N/A; Rtd Power: 0.063W; Rtd Voltage: 50V; Vendor: VISHAY; Vendor Part Number: CRCW040249K9FKED; Vendor Part Status: ACTIVE; Weight: 0.00065g
R119 = RESISTOR: RESISTOR, THICK FILM, 93.1k, -1%/+1%, 0.063W, 50V, -55DEGC/+155DEGC, 0402, SMD; ALT_SYMBOLS: RESC1005X40L,RESC1005X40M; AutoDoc File: https://notefied-dynamic-precision.com/DB/Apps/Desktop/Item/Object.aspx?id=59480; BU Name: DYNAMIC PRECISION GDANSK; Budget Currency: EUR; Budget Price: 0.012; Client Status: UNDER_REVIEW; Country of Origin: ISRAEL; Datasheet URL 1: http://www.vishay.com/docs/20035/dcrcwe3.pdf; Datasheet URL 2: N/A; Last Time Buy: N/A; Lead Time: 14; Max Oper Temp: +155DEGC; Max TC: +100PPM/DEGC; Max Tol: +1%; Min Oper Temp: -55DEGC; Min TC: -100PPM/DEGC; Min Tol: -1%; Mounting Type: SMD; PCB Package: 0402; Packing Size: 10000; Packing Type: TAPE_&_REEL; Part Number: 01-04673; Part Type: RESISTOR\0402\PRECISION; Resistor Type: THICK FILM; Revision: R001; RoHS Status: ROHS_COMPLIANT_WITH_EXEMPTION; Rtd Current: N/A; Rtd Power: 0.063W; Rtd Voltage: 50V; Vendor: VISHAY; Vendor Part Number: CRCW040293K1FKED; Vendor Part Status: ACTIVE; Weight: 0.00065g
R120 = RESISTOR: RESISTOR, THICK FILM, 10k, -1%/+1%, 0.063W, 50V, -55DEGC/+155DEGC, 0402, SMD; ALT_SYMBOLS: RESC1005X40A2L,RESC1005X40A2M; AutoDoc File: https://notefied-dynamic-precision.com/DB/Apps/Desktop/Item/Object.aspx?id=46198; BU Name: DYNAMIC PRECISION GDANSK; Budget Currency: EUR; Budget Price: 0.012; Client Status: UNDER_REVIEW; Country of Origin: ISRAEL; Datasheet URL 1: http://www.vishay.com/docs/20035/dcrcwe3.pdf; Datasheet URL 2: N/A; Last Time Buy: N/A; Lead Time: 14; Max Oper Temp: +155DEGC; Max TC: +100PPM/DEGC; Max Tol: +1%; Min Oper Temp: -55DEGC; Min TC: -100PPM/DEGC; Min Tol: -1%; Mounting Type: SMD; PCB Package: 0402; Packing Size: 10000; Packing Type: TAPE_&_REEL; Part Number: 01-00314; Part Type: RESISTOR\0402\PRECISION; Resistor Type: THICK FILM; Revision: R006; RoHS Status: ROHS_COMPLIANT_WITH_EXEMPTION; Rtd Current: N/A; Rtd Power: 0.063W; Rtd Voltage: 50V; Vendor: VISHAY; Vendor Part Number: CRCW040210K0FKED; Vendor Part Status: ACTIVE; Weight: 0.00060916g
R136 = RESISTOR: RESISTOR, THICK FILM, 57.6k, -1%/+1%, 0.063W, 50V, -55DEGC/+155DEGC, 0402, SMD; ALT_SYMBOLS: RESC1005X40A2L,RESC1005X40A2M; AutoDoc File: https://notefied-dynamic-precision.com/DB/Apps/Desktop/Item/Object.aspx?id=59463; BU Name: DYNAMIC PRECISION GDANSK; Budget Currency: EUR; Budget Price: 0.016; Country of Origin: ISRAEL; Datasheet URL 1: http://www.vishay.com/docs/20035/dcrcwe3.pdf; Datasheet URL 2: N/A; Last Time Buy: N/A; Lead Time: 18; Max Oper Temp: +155DEGC; Max TC: +100PPM/DEGC; Max Tol: +1%; Min Oper Temp: -55DEGC; Min TC: -100PPM/DEGC; Min Tol: -1%; Mounting Type: SMD; PCB Package: 0402; Packing Size: 10000; Packing Type: TAPE_&_REEL; Part Number: 01-04656; Part Type: RESISTOR\0402\PRECISION; Resistor Type: THICK FILM; Revision: R002; RoHS Status: ROHS_COMPLIANT; Rtd Current: N/A; Rtd Power: 0.063W; Rtd Voltage: 50V; Vendor: VISHAY; Vendor Part Number: CRCW040257K6FKED; Vendor Part Status: ACTIVE; Weight: 0.00065g
R137 = RESISTOR: RESISTOR, THICK FILM, 27k, -1%/+1%, 0.063W, 50V, -55DEGC/+155DEGC, 0402, SMD; ALT_SYMBOLS: RESC1005X40A2L,RESC1005X40A2M; AutoDoc File: https://notefied-dynamic-precision.com/DB/Apps/Desktop/Item/Object.aspx?id=46120; BU Name: DYNAMIC PRECISION GDANSK; Budget Currency: EUR; Budget Price: 0.012; Country of Origin: ISRAEL; Datasheet URL 1: http://www.vishay.com/docs/20035/dcrcwe3.pdf; Datasheet URL 2: N/A; Last Time Buy: N/A; Lead Time: 14; Max Oper Temp: +155DEGC; Max TC: +100PPM/DEGC; Max Tol: +1%; Min Oper Temp: -55DEGC; Min TC: -100PPM/DEGC; Min Tol: -1%; Mounting Type: SMD; PCB Package: 0402; Packing Size: 10000; Packing Type: TAPE_&_REEL; Part Number: 01-00236; Part Type: RESISTOR\0402\PRECISION; Resistor Type: THICK FILM; Revision: R008; RoHS Status: ROHS_COMPLIANT_WITH_EXEMPTION; Rtd Current: N/A; Rtd Power: 0.063W; Rtd Voltage: 50V; Vendor: VISHAY; Vendor Part Number: CRCW040227K0FKED; Vendor Part Status: ACTIVE; Weight: 0.00065g
TP1-TP6 = HOLE_PTH: NON COMPONENT, HOLE 0.6mm, PLATED HOLE; AutoDoc File: https://notefied-dynamic-precision.com/DB/Apps/Desktop/Item/Object.aspx?id=57336; BU Name: DYNAMIC PRECISION GDANSK; Part Number: 19-00057; Part Type: NON_COMPONENT\HOLE\PLATED; Revision: R001
U18 = IC_PM_LP5907-1_8_SOT23-5: IC, ANALOG, 0.25A LINEAR REGULATOR FOR RF AND ANALOG CIRCUITS–REQUIRES NO BYPASS CAPACITOR, VIN:2.2V TO 5.5V, VOUT: 1.8V, SOT23-5, SMD; ALT_SYMBOLS: SOT95P280X145-5A2L,SOT95P280X145-5A2M; AutoDoc File: https://notefied-dynamic-precision.com/DB/Apps/Desktop/Item/Object.aspx?id=113685; BU Name: DYNAMIC PRECISION GDANSK; Budget Currency: USD; Budget Price: 0.14; Client Status: UNDER_REVIEW; Datasheet URL 1: http://www.ti.com/lit/ds/symlink/lp5907.pdf; Datasheet URL 2: N/A; Last Time Buy: N/A; Max Oper Temp: +125DEGC; Min Oper Temp: -40DEGC; Mounting Type: SMD; PCB Package: SOT23-5; Packing Size: 3000; Packing Type: TAPE_&_REEL; Part Number: 18-32950; Part Type: IC\ANALOG\PM\REGULATOR; Revision: R001; RoHS Status: ROHS_COMPLIANT; Rtd Voltage: 1.8V; Vendor: TEXAS INSTRUMENTS; Vendor Part Number: LP5907MFX-1.8/NOPB; Vendor Part Status: ACTIVE; Weight: 0.0181g
U19 = IC_PM_TPS65130_QFN24: IC, ANALOG, DC-DC CONVERTER WITH POSITIVE AND NEGATIVE OUTPUTS, VIN:2.7V TO 5.5V, VOUT:-15V TO -2V/3.2V TO 15V, 0.2A, QFN24-EP, SMD; ALT_SYMBOLS: QFNFC50P400X400X100-25D2L,QFNFC50P400X400X100-25D2M; AutoDoc File: https://notefied-dynamic-precision.com/DB/Apps/Desktop/Item/Object.aspx?id=115284; BU Name: DYNAMIC PRECISION GDANSK; Budget Currency: USD; Budget Price: 1.30; Client Status: UNDER_REVIEW; Datasheet URL 1: http://www.ti.com/lit/ds/symlink/tps65130.pdf; Max Oper Temp: +85DEGC; Min Oper Temp: -40DEGC; Mounting Type: SMD; PCB Package: QFN24-EP; Packing Size: 3000; Packing Type: TAPE_&_REEL; Part Number: 18-33435; Part Type: IC\ANALOG\PM\DC-DC; Revision: R001; RoHS Status: ROHS_COMPLIANT; Rtd Current: 0.2A; Rtd Voltage: -15V TO -2V/3.2V TO 15V; Vendor: TEXAS INSTRUMENTS; Vendor Part Number: TPS65130RGER; Vendor Part Status: ACTIVE
U20 = IC_PM_TPS76801Q_HTSSOP20: IC, ANALOG, FAST TRANSIENT RESPONSE 1A LOW DROPOUT VOLTAGE REGULATOR, INPUT VOLTAGE:2.7V TO 10V, 1A, 1.2V TO 5.5V, HTSSOP20, SMD; ALT_SYMBOLS: TSSOP65P640X120-21L,TSSOP65P640X120-21M; AutoDoc File: https://notefied-dynamic-precision.com/DB/Apps/Desktop/Item/Object.aspx?id=20456; BU Name: DYNAMIC PRECISION GDANSK; Budget Currency: USD; Budget Price: 1.13; Country of Origin: TAIWAN; Datasheet URL 1: http://www.ti.com/lit/ds/symlink/tps76801.pdf; Datasheet URL 2: http://www.ti.com/litv/pdf/mhts001g; Last Time Buy: N/A; Lead Time: 6; Max Oper Temp: +125DEGC; Min Oper Temp: -40DEGC; Mounting Type: SMD; PCB Package: HTSSOP20; Packing Size: 70; Packing Type: TUBE; Part Number: 18-01495; Part Type: IC\ANALOG\PM\REGULATOR; Revision: R003; RoHS Status: ROHS_COMPLIANT; Rtd Voltage: 1.2V TO 5.5V; Vendor: TEXAS INSTRUMENTS; Vendor Part Number: TPS76801QPWPG4; Vendor Part Status: ACTIVE; Weight: 0.0749g
U21 = IC_PM_TPS7A4901_SON8: IC, ANALOG, 0.15A, HIGH PSRR, LOW-DROPOUT LINEAR REGULATOR, VIN:3V TO 36V, VOUT:1.194V TO 33V, SON8-EP, SMD; ALT_SYMBOLS: SON65P300X300X100-9A2L,SON65P300X300X100-9A2M; AutoDoc File: https://notefied-dynamic-precision.com/DB/Apps/Desktop/Item/Object.aspx?id=115315; BU Name: DYNAMIC PRECISION GDANSK; Budget Currency: USD; Budget Price: 1.1; Client Status: UNDER_REVIEW; Datasheet URL 1: http://www.ti.com/lit/ds/symlink/tps7a49.pdf; Datasheet URL 2: http://www.ti.com/lit/ml/mpds118j/mpds118j.pdf; Max Oper Temp: +125DEGC; Min Oper Temp: -40DEGC; Mounting Type: SMD; PCB Package: SON8-EP; Packing Size: 3000; Packing Type: TAPE_&_REEL; Part Number: 18-33442; Part Type: IC\ANALOG\PM\REGULATOR; Revision: R001; RoHS Status: ROHS_COMPLIANT; Rtd Voltage: 1.194V TO 33V; Vendor: TEXAS INSTRUMENTS; Vendor Part Number: TPS7A4901DRBR; Vendor Part Status: ACTIVE; Weight: 0.0219g
U22 = IC_PM_TPS7A3001_MSOP8: IC, ANALOG, –0.2A, ULTRALOW-NOISE, NEGATIVE LINEAR REGULATOR, VIN:–3V TO –36V, VOUT:–1.18V TO –35V, MSOP8-EP, SMD; ALT_SYMBOLS: SOP65P490X110-9B2L,SOP65P490X110-9B2M; AutoDoc File: https://notefied-dynamic-precision.com/DB/Apps/Desktop/Item/Object.aspx?id=115316; BU Name: DYNAMIC PRECISION GDANSK; Budget Currency: USD; Budget Price: 3.5; Client Status: UNDER_REVIEW; Datasheet URL 1: http://www.ti.com/lit/ds/symlink/tps7a3001-ep.pdf; Datasheet URL 2: http://www.ti.com/lit/ml/mpds046e/mpds046e.pdf; Max Oper Temp: +125DEGC; Min Oper Temp: -55DEGC; Mounting Type: SMD; PCB Package: MSOP8-EP; Packing Size: 250; Packing Type: TAPE_&_REEL; Part Number: 18-33443; Part Type: IC\ANALOG\PM\REGULATOR; Revision: R001; RoHS Status: ROHS_COMPLIANT; Rtd Voltage: –1.18V TO –35V; Vendor: TEXAS INSTRUMENTS; Vendor Part Status: ACTIVE; Weight: 0.0269g
U27 = IC_PM_TPS73101_SOT23-5: IC, ANALOG, 0.15A LOW DROPOUT REGULATOR WITH REVERSE CURRENT PROTECTION, VIN:1.7V TO 5.5V, VOUT:1.2V TO 5.5V, SOT23-5, SMD; ALT_SYMBOLS: SOT95P280X145-5A2L,SOT95P280X145-5A2M; AutoDoc File: https://notefied-dynamic-precision.com/DB/Apps/Desktop/Item/Object.aspx?id=116067; BU Name: DYNAMIC PRECISION GDANSK; Budget Currency: USD; Budget Price: 0.33; Client Status: UNDER_REVIEW; Datasheet URL 1: http://www.ti.com/lit/ds/symlink/tps731.pdf; Datasheet URL 2: http://www.ti.com/lit/ml/mpds018l/mpds018l.pdf; Max Oper Temp: +125DEGC; Min Oper Temp: -40DEGC; Mounting Type: SMD; PCB Package: SOT23-5; Packing Size: 3000; Packing Type: TAPE_&_REEL; Part Number: 18-33642; Part Type: IC\ANALOG\PM\REGULATOR; Revision: R001; RoHS Status: ROHS_COMPLIANT; Rtd Voltage: 1.2V TO 5.5V; Vendor: TEXAS INSTRUMENTS; Vendor Part Number: TPS73101DBVR; Vendor Part Status: ACTIVE; Weight: 0.0203g

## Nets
5V0: C103.1 C104.1 C121.1 C122.1 U18.1(IN) U18.3(EN) U20.6(IN) U20.7(IN) U27.1(IN) U27.3(EN) ; also on sheet 4 5
GND: C103.2 C104.2 C105.2 C106.2 C107.1 C108.2 C109.1 C110.2 C111.2 C112.2 C114.2 C115.2 C116.2 C117.2 C118.2 C119.2 C121.2 C122.2 C123.2 C124.2 C125.2 C127.2 C128.2 C130.2 C137.2 C138.2 C139.2 C140.2 C232.2 L26.2 R101.1 R104.2 R118.1 R120.1 R137.1 U18.2(GND) U19.2(PGND) U19.3(PGND) U19.19(AGND) U19.25(EGP) U20.1(GND/HSINK) U20.2(GND/HSINK) U20.3(GND) U20.5(nEN) U20.9(GND/HSINK) U20.10(GND/HSINK) U20.11(GND/HSINK) U20.12(GND/HSINK) U20.19(GND/HSINK) U20.20(GND/HSINK) U20.21(EGP) U21.4(GND) U21.9(EGP) U22.4(GND) U22.9(EGP) U27.2(GND) ; also on sheet 2 3 4 5 6 7
VDD_SWITCH: R136.1 U27.5(OUT) ; also on sheet 2 4
ET_1V8: C105.1 C106.1 TP6.1 U18.5(OUT) ; also on sheet 2
ET_3V3: C107.2 C123.1 C124.1 C125.1 C126.2 Q2.2(S) R96.2 R103.1 TP1.1 U19.5(INN) U19.6(INN) U20.13(OUT) U20.14(OUT) ; also on sheet 2
ET_+12V: C128.1 C130.1 C135.1 R117.2 TP4.1 U21.1(OUT) ; also on sheet 2
ET_-12V: C136.1 C139.1 C140.1 R119.2 TP2.1 U22.1(OUT) ; also on sheet 2
N1687235: C108.1 R96.1 U19.4(VIN) U19.8(ENP) U19.9(PSP) U19.10(ENN) U19.11(PSN)
N1687263: Q2.1(G) U19.7(BSW)
N1687273: C109.2 L25.1 Q2.3(D)
N1687279: CR10.2(ANODE) L25.2 U19.1(INP) U19.24(INP)
N1687281: C115.1 C116.1 C118.1 C127.1 CR10.1(CATHODE) R97.1 R102.1 TP5.1 U19.23(VPOS) U21.5(EN) U21.8(IN)
N1687325: C110.1 U19.21(CP)
N1687331: C111.1 U19.18(CN)
N1687341: C120.1 R97.2 R101.2 U19.22(FBP)
N1687345: CR11.1(CATHODE) L26.1 U19.13(OUTN) U19.14(OUTN)
N1687359: C114.1 C117.1 C119.1 C232.1 CR11.2(ANODE) R98.2 R100.1 TP3.1 U19.15(VNEG) U22.5(EN) U22.8(IN)
N1687363: C113.1 R98.1 R99.1 U19.16(FBN)
N1687373: C112.1 R99.2 U19.17(VREF)
N1687391: C113.2 R100.2
N1687461: C120.2 R102.2
N1687583: C126.1 R103.2 R104.1 U20.15(FB/NC)
N1687761: C135.2 R117.1 R118.2 U21.2(FB)
N1687779: C137.1 U21.6(NR/SS)
N1687817: C138.1 U22.6(NR/SS)
N1687829: C136.2 R119.1 R120.2 U22.2(FB)
N1936147: R136.2 R137.2 U27.4(NR/FB)

Not connected (* = marked no-connect by the designer): U18 4(NC)*; U19 12(NC)* 20(NC)*; U20 4(NC)* 8(NC)* 16(PG)* 17(NC)* 18(NC)*; U21 3(NC)* 7(NC)*; U22 3(NC)* 7(NC)*

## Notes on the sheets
sheet 1
- EnergyTrace Power Supply
- U24 VCC set at 3.77V, higher than
  switch supplies to prevent current
  through protection diodes
- WCS042B
